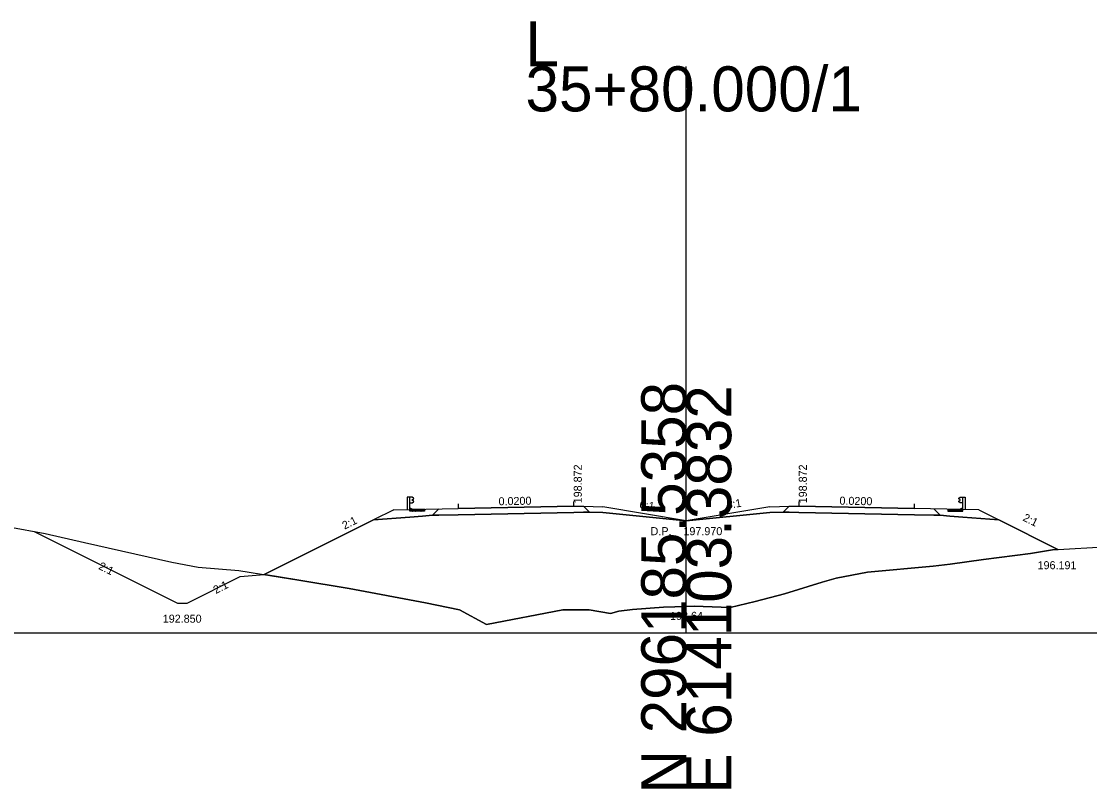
# Model space of a CAD drawing. Extents: x -81 to 616364, y 450 to 299952.
# Drawn here: x 541486 to 541552.5, y 119338.7 to 119386.4 of the extents above; entities that cross this region are included whole.
import ezdxf

# ---------------------------------------------------------------- set-up
doc = ezdxf.new("R2010")
doc.units = 0
for name, color, linetype in [('Exist XS Ground Line', 7, 'Continuous'), ('Old_Level_2', 7, 'Continuous'), ('Old_Level_3', 7, 'Continuous'), ('Old_Level_6', 7, 'Continuous'), ('Old_Level_63', 7, 'Continuous'), ('Prop XS DDE', 7, 'Continuous'), ('Prop XS Dump Level', 7, 'Continuous'), ('Prop XS Earthwork Shape', 7, 'Continuous'), ('Prop XS EOT Tick Mark', 7, 'Continuous'), ('Prop XS Finish Grade', 7, 'Continuous'), ('Prop XS Finish Grade Earthwork', 7, 'Continuous'), ('Prop XS Finish Grade Pavement', 7, 'Continuous'), ('Prop XS Hydro Elevations', 7, 'Continuous'), ('Prop XS Label Text', 7, 'Continuous'), ('Prop XS Pvmt Edge Slope', 7, 'Continuous'), ('Prop XS Side Slope Text', 7, 'Continuous'), ('Prop XS Subgrade Earthwork', 7, 'Continuous')]:
    doc.layers.add(name, color=color, linetype=linetype)

msp = doc.modelspace()

# ---------------------------------------------------------------- linework, layer by layer
at = {"layer": 'Exist XS Ground Line'}
for p, q in [((541485.214, 119354.961), (541487.474, 119354.55)), ((541487.474, 119354.55), (541489.929, 119353.988)), ((541489.929, 119353.988), (541495.366, 119352.756)), ((541548.778, 119353.31), (541550.141, 119353.537)), ((541550.141, 119353.537), (541553.693, 119353.738)), ((541543.788, 119352.637), (541545.845, 119352.925)), ((541545.845, 119352.925), (541548.778, 119353.31)), ((541495.366, 119352.756), (541497, 119352.454)), ((541497, 119352.454), (541499.524, 119352.241)), ((541499.524, 119352.241), (541500.937, 119352.013)), ((541538.646, 119352.136), (541542.718, 119352.511)), ((541542.718, 119352.511), (541543.788, 119352.637)), ((541500.937, 119352.013), (541503.257, 119351.647)), ((541503.257, 119351.647), (541506.394, 119351.13)), ((541533.485, 119350.795), (541535.813, 119351.512)), ((541535.813, 119351.512), (541536.688, 119351.765)), ((541536.688, 119351.765), (541538.646, 119352.136)), ((541506.394, 119351.13), (541511.15, 119350.238)), ((541511.15, 119350.238), (541513.248, 119349.789)), ((541530.098, 119349.947), (541531.659, 119350.323)), ((541531.659, 119350.323), (541533.485, 119350.795)), ((541513.248, 119349.789), (541514.945, 119348.875)), ((541514.945, 119348.875), (541519.693, 119349.802)), ((541519.693, 119349.802), (541521.321, 119349.804)), ((541521.321, 119349.804), (541522.66, 119349.577)), ((541522.66, 119349.577), (541523.162, 119349.715)), ((541523.162, 119349.715), (541524.025, 119349.817)), ((541524.025, 119349.817), (541525.947, 119349.965)), ((541525.947, 119349.965), (541527.365, 119350.008)), ((541527.365, 119350.008), (541527.852, 119350.023)), ((541527.852, 119350.023), (541530.098, 119349.947))]:
    msp.add_line(p, q, dxfattribs=at)
at = {"layer": 'Old_Level_2'}
for p, q in [((541544.565, 119356.136), (541544.355, 119356.031)), ((541544.565, 119355.931), (541544.565, 119356.136)), ((541543.645, 119356.056), (541543.645, 119355.931)), ((541543.645, 119356.056), (541544.355, 119356.031)), ((541543.645, 119355.931), (541544.565, 119355.931)), ((541543.692, 119356.033), (541543.667, 119356.015)), ((541543.667, 119356.015), (541543.707, 119356.005)), ((541543.707, 119356.005), (541543.692, 119356.033)), ((541543.8, 119355.983), (541543.775, 119355.965)), ((541543.775, 119355.965), (541543.816, 119355.955)), ((541543.816, 119355.955), (541543.8, 119355.983)), ((541543.882, 119355.996), (541543.873, 119355.968)), ((541543.873, 119355.968), (541543.903, 119355.967)), ((541543.903, 119355.967), (541543.882, 119355.996)), ((541544.01, 119356.014), (541543.985, 119355.996)), ((541543.985, 119355.996), (541544.025, 119355.986)), ((541544.025, 119355.986), (541544.01, 119356.014)), ((541544.105, 119355.983), (541544.08, 119355.965)), ((541544.08, 119355.965), (541544.12, 119355.955)), ((541544.12, 119355.955), (541544.105, 119355.983)), ((541544.186, 119355.996), (541544.178, 119355.968)), ((541544.178, 119355.968), (541544.207, 119355.967)), ((541544.207, 119355.967), (541544.186, 119355.996)), ((541544.31, 119355.982), (541544.285, 119355.964)), ((541544.285, 119355.964), (541544.325, 119355.954)), ((541544.325, 119355.954), (541544.31, 119355.982)), ((541544.409, 119355.983), (541544.384, 119355.965)), ((541544.384, 119355.965), (541544.425, 119355.955)), ((541544.425, 119355.955), (541544.409, 119355.983)), ((541544.468, 119356.02), (541544.506, 119356.031)), ((541544.502, 119356.009), (541544.468, 119356.02)), ((541544.506, 119356.031), (541544.502, 119356.009))]:
    msp.add_line(p, q, dxfattribs=at)
for centre in [(541543.653, 119356.014), (541543.658, 119355.99), (541543.661, 119356.045), (541543.661, 119355.944), (541543.68, 119355.977), (541543.702, 119355.95), (541543.706, 119356.046), (541543.708, 119355.99), (541543.72, 119355.967), (541543.73, 119356.026), (541543.74, 119356.006), (541543.743, 119355.956), (541543.749, 119356.043), (541543.753, 119356.015), (541543.757, 119355.991), (541543.77, 119355.944), (541543.773, 119355.986), (541543.779, 119356.042), (541543.795, 119355.942), (541543.797, 119356.021), (541543.8, 119356.015), (541543.822, 119355.986), (541543.823, 119355.946), (541543.84, 119356), (541543.846, 119355.97), (541543.847, 119356.025), (541543.867, 119355.941), (541543.871, 119356.038), (541543.873, 119355.987), (541543.894, 119356.015), (541543.895, 119355.942), (541543.896, 119356.022), (541543.903, 119355.98), (541543.925, 119355.967), (541543.928, 119356.037), (541543.94, 119356.001), (541543.942, 119355.941), (541543.944, 119356.006), (541543.948, 119355.956), (541543.958, 119356.014), (541543.962, 119355.99), (541543.973, 119355.965), (541543.984, 119355.942), (541543.989, 119356.037), (541543.998, 119355.976), (541544.019, 119355.94), (541544.024, 119355.967), (541544.029, 119356.024), (541544.044, 119356.006), (541544.048, 119355.956), (541544.058, 119356.015), (541544.062, 119355.991), (541544.063, 119356.032), (541544.078, 119355.986), (541544.1, 119355.942), (541544.105, 119356.015), (541544.136, 119355.971), (541544.138, 119356.021), (541544.144, 119356), (541544.156, 119355.949), (541544.177, 119355.987), (541544.178, 119356.024), (541544.199, 119356.015), (541544.2, 119355.942), (541544.208, 119355.98), (541544.226, 119355.997), (541544.229, 119355.967), (541544.231, 119355.942), (541544.244, 119356.001), (541544.249, 119356.006), (541544.253, 119355.956), (541544.262, 119356.014), (541544.267, 119355.99), (541544.287, 119355.942), (541544.295, 119355.994), (541544.298, 119356.016), (541544.31, 119356.014), (541544.329, 119355.967), (541544.339, 119356.026), (541544.349, 119356.006), (541544.352, 119355.956), (541544.362, 119356.015), (541544.366, 119355.991), (541544.382, 119355.986), (541544.397, 119356.035), (541544.404, 119356.005), (541544.404, 119355.942), (541544.429, 119356.011), (541544.435, 119356.044), (541544.444, 119355.974), (541544.445, 119355.939), (541544.454, 119356.007), (541544.464, 119356.066), (541544.47, 119355.948), (541544.475, 119356.041), (541544.486, 119356.053), (541544.49, 119356.029), (541544.491, 119355.993), (541544.496, 119356.081), (541544.495, 119355.981), (541544.499, 119355.974), (541544.512, 119355.945), (541544.523, 119356.026), (541544.525, 119356.052), (541544.528, 119355.987), (541544.546, 119356.063), (541544.548, 119356.11), (541544.548, 119355.949), (541544.55, 119356.015)]:
    msp.add_circle(centre, 0.00196, dxfattribs=at)
for centre, start, end in [((541543.644, 119355.956), 307.99378, 52.00622), ((541543.738, 119355.929), 49.28893, 130.71107), ((541543.83, 119356.027), 170.20024, 7.80025), ((541543.838, 119355.93), 21.99756, 158.00245), ((541543.947, 119356.026), 188.5188, 349.48169), ((541544.043, 119355.929), 49.28893, 130.71107), ((541544.101, 119356.021), 124.58368, 53.41682), ((541544.142, 119355.93), 21.99756, 158.00245), ((541544.201, 119356.022), 206.33478, 331.66571), ((541544.251, 119356.026), 269.97407, 330.0388), ((541544.347, 119355.929), 49.28893, 130.71107), ((541544.536, 119356.076), 131.00569, 228.99431)]:
    msp.add_arc(centre, 0.00196, start, end, dxfattribs=at)
at = {"layer": 'Old_Level_3'}
for p, q in [((541510.165, 119356.136), (541510.375, 119356.031)), ((541510.165, 119355.931), (541510.165, 119356.136)), ((541511.085, 119355.931), (541510.165, 119355.931)), ((541510.224, 119356.031), (541510.228, 119356.009)), ((541510.261, 119356.02), (541510.224, 119356.031)), ((541510.228, 119356.009), (541510.261, 119356.02)), ((541510.305, 119355.955), (541510.32, 119355.983)), ((541510.345, 119355.965), (541510.305, 119355.955)), ((541510.32, 119355.983), (541510.345, 119355.965)), ((541511.085, 119356.056), (541510.375, 119356.031)), ((541510.405, 119355.954), (541510.42, 119355.982)), ((541510.445, 119355.964), (541510.405, 119355.954)), ((541510.42, 119355.982), (541510.445, 119355.964)), ((541510.523, 119355.967), (541510.544, 119355.996)), ((541510.552, 119355.968), (541510.523, 119355.967)), ((541510.544, 119355.996), (541510.552, 119355.968)), ((541510.609, 119355.955), (541510.625, 119355.983)), ((541510.65, 119355.965), (541510.609, 119355.955)), ((541510.625, 119355.983), (541510.65, 119355.965)), ((541510.705, 119355.986), (541510.72, 119356.014)), ((541510.745, 119355.996), (541510.705, 119355.986)), ((541510.72, 119356.014), (541510.745, 119355.996)), ((541510.827, 119355.967), (541510.848, 119355.996)), ((541510.856, 119355.968), (541510.827, 119355.967)), ((541510.848, 119355.996), (541510.856, 119355.968)), ((541510.914, 119355.955), (541510.929, 119355.983)), ((541510.954, 119355.965), (541510.914, 119355.955)), ((541510.929, 119355.983), (541510.954, 119355.965)), ((541511.022, 119356.005), (541511.038, 119356.033)), ((541511.063, 119356.015), (541511.022, 119356.005)), ((541511.038, 119356.033), (541511.063, 119356.015)), ((541511.085, 119356.056), (541511.085, 119355.931))]:
    msp.add_line(p, q, dxfattribs=at)
for centre in [(541510.179, 119356.015), (541510.182, 119356.11), (541510.182, 119355.949), (541510.184, 119356.063), (541510.201, 119355.987), (541510.205, 119356.052), (541510.206, 119356.026), (541510.218, 119355.945), (541510.231, 119355.974), (541510.234, 119356.081), (541510.234, 119355.981), (541510.238, 119355.993), (541510.24, 119356.029), (541510.244, 119356.053), (541510.254, 119356.041), (541510.259, 119355.948), (541510.266, 119356.066), (541510.276, 119356.007), (541510.284, 119355.939), (541510.285, 119355.974), (541510.294, 119356.044), (541510.301, 119356.011), (541510.325, 119355.942), (541510.326, 119356.005), (541510.333, 119356.035), (541510.348, 119355.986), (541510.363, 119355.991), (541510.368, 119356.015), (541510.377, 119355.956), (541510.381, 119356.006), (541510.391, 119356.026), (541510.401, 119355.967), (541510.42, 119356.014), (541510.431, 119356.016), (541510.434, 119355.994), (541510.443, 119355.942), (541510.463, 119355.99), (541510.467, 119356.014), (541510.477, 119355.956), (541510.481, 119356.006), (541510.486, 119356.001), (541510.499, 119355.942), (541510.5, 119355.967), (541510.503, 119355.997), (541510.522, 119355.98), (541510.53, 119355.942), (541510.531, 119356.015), (541510.551, 119356.024), (541510.552, 119355.987), (541510.573, 119355.949), (541510.585, 119356), (541510.592, 119356.021), (541510.594, 119355.971), (541510.625, 119356.015), (541510.63, 119355.942), (541510.652, 119355.986), (541510.666, 119356.032), (541510.668, 119355.991), (541510.672, 119356.015), (541510.682, 119355.956), (541510.686, 119356.006), (541510.7, 119356.024), (541510.705, 119355.967), (541510.711, 119355.94), (541510.732, 119355.976), (541510.741, 119356.037), (541510.746, 119355.942), (541510.757, 119355.965), (541510.768, 119355.99), (541510.772, 119356.014), (541510.781, 119355.956), (541510.785, 119356.006), (541510.788, 119355.941), (541510.79, 119356.001), (541510.802, 119356.037), (541510.805, 119355.967), (541510.826, 119355.98), (541510.833, 119356.022), (541510.835, 119356.015), (541510.835, 119355.942), (541510.857, 119355.987), (541510.859, 119356.038), (541510.863, 119355.941), (541510.883, 119356.025), (541510.884, 119355.97), (541510.89, 119356), (541510.907, 119355.946), (541510.908, 119355.986), (541510.929, 119356.015), (541510.933, 119356.021), (541510.934, 119355.942), (541510.951, 119356.042), (541510.957, 119355.986), (541510.959, 119355.944), (541510.972, 119355.991), (541510.977, 119356.015), (541510.98, 119356.043), (541510.986, 119355.956), (541510.99, 119356.006), (541511, 119356.026), (541511.01, 119355.967), (541511.022, 119355.99), (541511.024, 119356.046), (541511.028, 119355.95), (541511.05, 119355.977), (541511.069, 119356.045), (541511.069, 119355.944), (541511.072, 119355.99), (541511.076, 119356.014)]:
    msp.add_circle(centre, 0.00196, dxfattribs=at)
for centre, start, end in [((541510.194, 119356.076), 311.00569, 48.99431), ((541510.382, 119355.929), 49.28893, 130.71107), ((541510.479, 119356.026), 209.9612, 270.02593), ((541510.529, 119356.022), 208.33429, 333.66522), ((541510.587, 119355.93), 21.99755, 158.00244), ((541510.628, 119356.021), 126.58318, 55.41633), ((541510.687, 119355.929), 49.28893, 130.71107), ((541510.783, 119356.026), 190.51831, 351.4812), ((541510.892, 119355.93), 21.99755, 158.00244), ((541510.9, 119356.027), 172.19975, 9.79976), ((541510.991, 119355.929), 49.28893, 130.71107), ((541511.086, 119355.956), 127.99378, 232.00622)]:
    msp.add_arc(centre, 0.00196, start, end, dxfattribs=at)
at = {"layer": 'Old_Level_6'}
for p, q in [((541513.165, 119356.093), (541520.365, 119356.237)), ((541534.365, 119356.237), (541541.565, 119356.093))]:
    msp.add_line(p, q, dxfattribs=at)
at = {"layer": 'Old_Level_63'}
for p, q in [((541527.365, 119348.365), (541527.365, 119383.605)), ((541452.365, 119348.365), (541527.365, 119348.365)), ((541527.365, 119348.365), (541602.365, 119348.365))]:
    msp.add_line(p, q, dxfattribs=at)
at = {"layer": 'Prop XS DDE'}
for p, q in [((541486.789, 119354.674), (541495.708, 119350.215)), ((541496.308, 119350.215), (541499.61, 119351.866)), ((541499.61, 119351.866), (541501.11, 119351.986)), ((541495.708, 119350.215), (541496.308, 119350.215))]:
    msp.add_line(p, q, dxfattribs=at)
at = {"layer": 'Prop XS Dump Level'}
for p, q in [((541513.165, 119356.093), (541520.365, 119356.237)), ((541534.365, 119356.237), (541541.565, 119356.093))]:
    msp.add_line(p, q, dxfattribs=at)
at = {"layer": 'Prop XS Earthwork Shape'}
for points in [[(541533.485, 119350.795), (541535.813, 119351.512), (541536.688, 119351.765), (541538.646, 119352.136), (541542.718, 119352.511), (541543.788, 119352.637), (541545.845, 119352.925), (541548.778, 119353.31), (541550.141, 119353.537), (541550.479, 119353.556), (541546.814, 119355.389), (541544.565, 119355.568), (541543.765, 119355.632), (541543.153, 119355.681), (541542.765, 119355.689), (541541.565, 119355.713), (541534.365, 119355.857), (541533.765, 119355.869), (541533.392, 119355.877), (541532.565, 119355.844), (541527.365, 119355.334), (541522.165, 119355.844), (541521.337, 119355.877), (541520.965, 119355.869), (541520.365, 119355.857), (541513.165, 119355.713), (541511.965, 119355.689), (541511.577, 119355.681), (541510.965, 119355.632), (541510.165, 119355.568), (541507.915, 119355.388), (541501.11, 119351.986), (541503.257, 119351.647), (541506.394, 119351.13), (541511.15, 119350.238), (541513.248, 119349.789), (541514.945, 119348.875), (541519.693, 119349.802), (541521.321, 119349.804), (541522.66, 119349.577), (541523.162, 119349.715), (541524.025, 119349.817), (541525.947, 119349.965), (541527.365, 119350.008), (541527.852, 119350.023), (541530.098, 119349.947), (541531.659, 119350.323)], [(541542.765, 119355.689), (541543.153, 119355.681), (541543.765, 119355.632), (541544.565, 119355.568), (541546.814, 119355.389), (541550.479, 119353.556), (541550.141, 119353.537), (541548.778, 119353.31), (541545.845, 119352.925), (541543.788, 119352.637), (541542.718, 119352.511), (541538.646, 119352.136), (541536.688, 119351.765), (541535.813, 119351.512), (541533.485, 119350.795), (541531.659, 119350.323), (541530.098, 119349.947), (541527.852, 119350.023), (541527.365, 119350.008), (541525.947, 119349.965), (541524.025, 119349.817), (541523.162, 119349.715), (541522.66, 119349.577), (541521.321, 119349.804), (541519.693, 119349.802), (541514.945, 119348.875), (541513.248, 119349.789), (541511.15, 119350.238), (541506.394, 119351.13), (541503.257, 119351.647), (541501.11, 119351.986), (541507.915, 119355.388), (541510.165, 119355.568), (541510.965, 119355.632), (541511.577, 119355.681), (541511.965, 119355.689), (541513.165, 119355.713), (541520.365, 119355.857), (541520.965, 119355.869), (541521.337, 119355.877), (541522.165, 119355.844), (541527.365, 119355.334), (541532.565, 119355.844), (541533.392, 119355.877), (541533.765, 119355.869), (541534.365, 119355.857), (541541.565, 119355.713)], [(541510.965, 119355.632), (541511.577, 119355.681), (541511.965, 119355.689), (541513.165, 119355.713), (541520.365, 119355.857), (541520.965, 119355.869), (541521.337, 119355.877), (541522.165, 119355.844), (541527.365, 119355.334), (541532.565, 119355.844), (541533.392, 119355.877), (541533.765, 119355.869), (541534.365, 119355.857), (541541.565, 119355.713), (541542.765, 119355.689), (541543.153, 119355.681), (541543.765, 119355.632), (541544.565, 119355.568), (541546.814, 119355.389), (541550.479, 119353.556), (541550.141, 119353.537), (541548.778, 119353.31), (541545.845, 119352.925), (541543.788, 119352.637), (541542.718, 119352.511), (541538.646, 119352.136), (541536.688, 119351.765), (541535.813, 119351.512), (541533.485, 119350.795), (541531.659, 119350.323), (541530.098, 119349.947), (541527.852, 119350.023), (541527.365, 119350.008), (541525.947, 119349.965), (541524.025, 119349.817), (541523.162, 119349.715), (541522.66, 119349.577), (541521.321, 119349.804), (541519.693, 119349.802), (541514.945, 119348.875), (541513.248, 119349.789), (541511.15, 119350.238), (541506.394, 119351.13), (541503.257, 119351.647), (541501.11, 119351.986), (541507.915, 119355.388), (541510.165, 119355.568)], [(541520.365, 119355.857), (541513.165, 119355.713), (541511.965, 119355.689), (541511.577, 119355.681), (541510.965, 119355.632), (541510.165, 119355.568), (541507.915, 119355.388), (541501.11, 119351.986), (541503.257, 119351.647), (541506.394, 119351.13), (541511.15, 119350.238), (541513.248, 119349.789), (541514.945, 119348.875), (541519.693, 119349.802), (541521.321, 119349.804), (541522.66, 119349.577), (541523.162, 119349.715), (541524.025, 119349.817), (541525.947, 119349.965), (541527.365, 119350.008), (541527.852, 119350.023), (541530.098, 119349.947), (541531.659, 119350.323), (541533.485, 119350.795), (541535.813, 119351.512), (541536.688, 119351.765), (541538.646, 119352.136), (541542.718, 119352.511), (541543.788, 119352.637), (541545.845, 119352.925), (541548.778, 119353.31), (541550.141, 119353.537), (541550.479, 119353.556), (541546.814, 119355.389), (541544.565, 119355.568), (541543.765, 119355.632), (541543.153, 119355.681), (541542.765, 119355.689), (541541.565, 119355.713), (541534.365, 119355.857), (541533.765, 119355.869), (541533.392, 119355.877), (541532.565, 119355.844), (541527.365, 119355.334), (541522.165, 119355.844), (541521.337, 119355.877), (541520.965, 119355.869)]]:
    msp.add_lwpolyline(points, close=True, dxfattribs=at)
at = {"layer": 'Prop XS EOT Tick Mark'}
for p, q in [((541513.165, 119356.398), (541513.165, 119356.093)), ((541520.365, 119356.237), (541520.365, 119356.542)), ((541534.365, 119356.542), (541534.365, 119356.237)), ((541541.565, 119356.093), (541541.565, 119356.398))]:
    msp.add_line(p, q, dxfattribs=at)
at = {"layer": 'Prop XS Finish Grade'}
for p, q in [((541520.965, 119356.249), (541522.165, 119356.201)), ((541527.365, 119355.334), (541522.165, 119356.201)), ((541532.565, 119356.201), (541527.365, 119355.334)), ((541532.565, 119356.201), (541533.765, 119356.249)), ((541509.165, 119356.013), (541507.916, 119355.389)), ((541509.165, 119356.013), (541510.165, 119356.033)), ((541545.565, 119356.013), (541544.565, 119356.033)), ((541545.565, 119356.013), (541546.814, 119355.388))]:
    msp.add_line(p, q, dxfattribs=at)
at = {"layer": 'Prop XS Finish Grade Earthwork'}
for p, q in [((541507.916, 119355.389), (541501.11, 119351.986)), ((541546.814, 119355.388), (541550.479, 119353.556))]:
    msp.add_line(p, q, dxfattribs=at)
at = {"layer": 'Prop XS Finish Grade Pavement'}
for p, q in [((541520.365, 119356.237), (541513.165, 119356.093)), ((541520.365, 119356.237), (541520.965, 119356.249)), ((541533.765, 119356.249), (541534.365, 119356.237)), ((541541.565, 119356.093), (541534.365, 119356.237)), ((541510.165, 119356.033), (541513.165, 119356.093)), ((541544.565, 119356.033), (541541.565, 119356.093))]:
    msp.add_line(p, q, dxfattribs=at)
at = {"layer": 'Prop XS Label Text'}
for p, q in [((541510.165, 119356.795), (541510.012, 119356.795)), ((541510.012, 119356.795), (541510.012, 119356.033)), ((541510.317, 119356.795), (541510.165, 119356.795)), ((541510.165, 119356.033), (541510.165, 119356.795)), ((541510.406, 119356.734), (541510.317, 119356.795)), ((541544.324, 119356.734), (541544.412, 119356.795)), ((541544.412, 119356.795), (541544.565, 119356.795)), ((541544.565, 119356.033), (541544.565, 119356.795)), ((541544.565, 119356.795), (541544.717, 119356.795)), ((541544.717, 119356.795), (541544.717, 119356.033)), ((541510.165, 119356.45), (541510.317, 119356.45)), ((541510.317, 119356.637), (541510.406, 119356.698)), ((541510.317, 119356.608), (541510.317, 119356.637)), ((541510.406, 119356.547), (541510.317, 119356.608)), ((541510.317, 119356.45), (541510.406, 119356.51)), ((541510.415, 119356.716), (541510.406, 119356.734)), ((541510.406, 119356.698), (541510.415, 119356.716)), ((541510.415, 119356.529), (541510.406, 119356.547)), ((541510.406, 119356.51), (541510.415, 119356.529)), ((541544.315, 119356.716), (541544.324, 119356.734)), ((541544.324, 119356.698), (541544.315, 119356.716)), ((541544.315, 119356.529), (541544.324, 119356.547)), ((541544.324, 119356.51), (541544.315, 119356.529)), ((541544.412, 119356.637), (541544.324, 119356.698)), ((541544.324, 119356.547), (541544.412, 119356.608)), ((541544.412, 119356.45), (541544.324, 119356.51)), ((541544.412, 119356.608), (541544.412, 119356.637)), ((541544.565, 119356.45), (541544.412, 119356.45))]:
    msp.add_line(p, q, dxfattribs=at)
at = {"layer": 'Prop XS Pvmt Edge Slope'}
for p, q in [((541520.965, 119356.249), (541521.337, 119355.877)), ((541533.392, 119355.877), (541533.765, 119356.249)), ((541511.577, 119355.681), (541511.965, 119356.069)), ((541542.765, 119356.069), (541543.153, 119355.681))]:
    msp.add_line(p, q, dxfattribs=at)
at = {"layer": 'Prop XS Subgrade Earthwork'}
for p, q in [((541507.915, 119355.388), (541510.165, 119355.568)), ((541510.165, 119355.568), (541510.965, 119355.632)), ((541510.965, 119355.632), (541511.577, 119355.681)), ((541511.577, 119355.681), (541511.965, 119355.689)), ((541511.965, 119355.689), (541513.165, 119355.713)), ((541520.365, 119355.857), (541513.165, 119355.713)), ((541520.365, 119355.857), (541520.965, 119355.869)), ((541520.965, 119355.869), (541521.337, 119355.877)), ((541521.337, 119355.877), (541522.165, 119355.844)), ((541527.365, 119355.334), (541522.165, 119355.844)), ((541527.365, 119355.334), (541532.565, 119355.844)), ((541532.565, 119355.844), (541533.392, 119355.877)), ((541533.392, 119355.877), (541533.765, 119355.869)), ((541533.765, 119355.869), (541534.365, 119355.857)), ((541541.565, 119355.713), (541534.365, 119355.857)), ((541541.565, 119355.713), (541542.765, 119355.689)), ((541542.765, 119355.689), (541543.153, 119355.681)), ((541543.153, 119355.681), (541543.765, 119355.632)), ((541543.765, 119355.632), (541544.565, 119355.568)), ((541544.565, 119355.568), (541546.814, 119355.389))]:
    msp.add_line(p, q, dxfattribs=at)

# ---------------------------------------------------------------- texts
at = {"layer": 'Old_Level_63'}
for s, p in [('L', (541517.356, 119383.605)), ('35+80.000/1', (541517.365, 119380.805))]:
    msp.add_text(s, height=2.8, dxfattribs=at).set_placement(p)
for s, p in [('N 296185.5358', (541527.365, 119338.365)), ('E 614103.3832', (541530.165, 119338.365))]:
    msp.add_text(s, height=2.8, rotation=90, dxfattribs=at).set_placement(p)
at = {"layer": 'Prop XS Dump Level'}
for s, p in [('Case1', (541522.165, 119356.189)), ('MGSP-L', (541522.165, 119356.189)), ('Case1', (541532.565, 119356.189)), ('MGSP-R', (541532.565, 119356.189)), ('Case4', (541510.165, 119356.033)), ('Case4', (541544.521, 119356.033)), ('MGDP', (541527.365, 119355.322))]:
    msp.add_text(s, height=0.0122, dxfattribs=at).set_placement(p)
at = {"layer": 'Prop XS Hydro Elevations'}
for rotation, p in [(333.43495, (541490.76, 119352.353)), (26.56505, (541498.093, 119350.772))]:
    msp.add_text('2:1', height=0.5, rotation=rotation, dxfattribs=at).set_placement(p)
msp.add_text('192.850', height=0.5, dxfattribs=at).set_placement((541494.798, 119348.995))
at = {"layer": 'Prop XS Side Slope Text'}
for s, rotation, p in [(' 198.872', 90, (541520.865, 119356.237)), (' 198.872', 90, (541534.865, 119356.237)), (' 198.87', 90, (541520.865, 119356.237)), (' 198.87', 90, (541534.865, 119356.237)), ('0.0200', 1.14576, (541515.692, 119356.296)), ('0.0200', 358.85424, (541536.892, 119356.339)), ('6:1', 350.53768, (541524.423, 119356.129)), ('6:1', 9.46233, (541529.916, 119356.064)), ('2:1', 26.56512, (541506.111, 119354.78)), ('2:1', 333.43495, (541548.255, 119355.369))]:
    msp.add_text(s, height=0.5, rotation=rotation, dxfattribs=at).set_placement(p)
for s, p in [('D.P.    197.970', (541525.145, 119354.44)), ('196.191', (541549.22, 119352.321)), ('192.64', (541526.355, 119349.17))]:
    msp.add_text(s, height=0.5, dxfattribs=at).set_placement(p)

doc.saveas('drawing.dxf')
